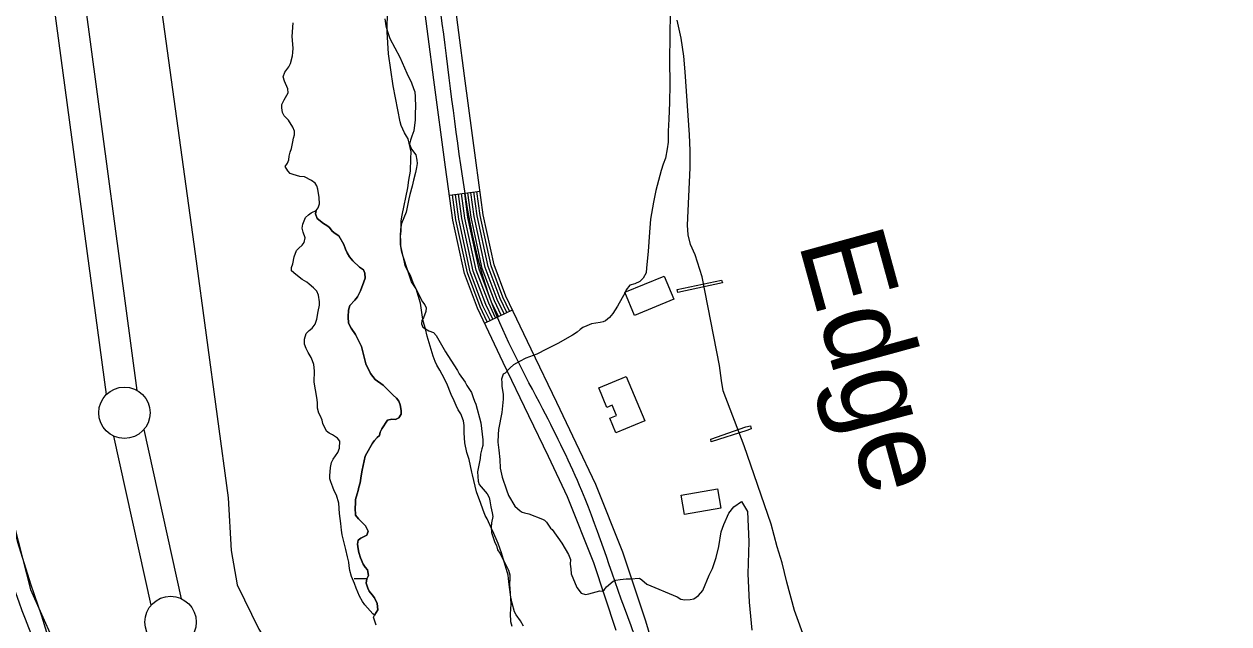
# Model space of a CAD drawing. Extents: x 3161564 to 3199464, y 849354 to 874788.
# Drawn here: x 3174720 to 3175892, y 859669 to 860252 of the extents above; entities that cross this region are included whole.
import ezdxf

# ---------------------------------------------------------------- set-up
doc = ezdxf.new("R2010")
doc.units = 0
for name, color, linetype in [('V-BLDG-OTLN', 7, 'Continuous'), ('V-CHAN-DOCK', 7, 'Continuous'), ('V-LEVE-TOET', 7, 'Continuous'), ('V-RIVR-IDEN', 7, 'Continuous'), ('V-ROAD-CNTR', 7, 'Continuous'), ('V-SITE-VEGE', 7, 'Continuous'), ('V-SURV-LINE', 7, 'Continuous'), ('V-TOPO-SHOR', 7, 'Continuous'), ('V-WETL-SWMP', 7, 'Continuous')]:
    doc.layers.add(name, color=color, linetype=linetype)

msp = doc.modelspace()

# ---------------------------------------------------------------- linework, layer by layer
at = {"layer": 'V-BLDG-OTLN'}
for points in [[(3175313.7, 859969.1), (3175304.4, 859991.7), (3175342.5, 860007.4), (3175351.8, 859984.8)], [(3175305.7, 859909.7), (3175323.7, 859866.5), (3175295.5, 859854.8), (3175289.6, 859869), (3175296.1, 859871.7), (3175291.9, 859881.8), (3175286.7, 859879.6), (3175278.9, 859898.5)], [(3175397.6, 859781.7), (3175362.3, 859775.4), (3175358.9, 859794.1), (3175394.2, 859800.5)]]:
    msp.add_lwpolyline(points, close=True, dxfattribs=at)
at = {"layer": 'V-CHAN-DOCK'}
for points in [[(3175398.3, 860003.2), (3175399.1, 860000.7), (3175355.7, 859991.5), (3175355.2, 859994.3), (3175398.3, 860003.2)], [(3175427.2, 859858.7), (3175422.8, 859857.2), (3175388.3, 859846.1), (3175387.8, 859848.8), (3175422, 859860.6), (3175426.3, 859861.6), (3175427.2, 859858.7)]]:
    msp.add_lwpolyline(points, dxfattribs=at)
at = {"layer": 'V-LEVE-TOET'}
for points in [[(3174822.8, 860492.3), (3174886.6, 860028.8), (3174918.6, 859791.7), (3174921.6, 859740.6), (3174927.3, 859707.2), (3174948.6, 859664), (3174965.5, 859636.6), (3174988.5, 859602.2), (3175016.5, 859565.4), (3175046.5, 859530.1), (3175135.4, 859413.8), (3175254.4, 859247.9), (3175400.5, 859075)], [(3175459.5, 858433.4), (3175350.4, 858733.6), (3175314.5, 858825.1), (3175277.8, 858898.4), (3175238, 858970.2), (3175193.8, 859031.2), (3175113.9, 859131.1), (3174929.1, 859367), (3174810.7, 859521.6), (3174784.7, 859565), (3174763.7, 859601.7), (3174748.5, 859640.6), (3174737.5, 859676.7), (3174726.8, 859707.8), (3174714.3, 859748.2), (3174706.3, 859779.3), (3174701.8, 859809.9), (3174688.7, 859906), (3174645.1, 860283.3)]]:
    msp.add_lwpolyline(points, dxfattribs=at)
at = {"layer": 'V-ROAD-CNTR'}
for p, q in [((3175133.7, 860085.9), (3175163.5, 860089.9)), ((3175167.9, 859961.5), (3175195, 859974.4))]:
    msp.add_line(p, q, dxfattribs=at)
for points in [[(3175335.6, 859596.5), (3175337, 859622.9), (3175335.1, 859636.8), (3175324.6, 859671.7), (3175302.2, 859738.8), (3175276.2, 859804.6), (3175257.1, 859844.7), (3175238.2, 859884.3), (3175213.2, 859936.4), (3175188.5, 859987.9), (3175177.1, 860018.2), (3175166.6, 860066.8), (3175159.7, 860117.4), (3175148.4, 860202), (3175137.5, 860286.7), (3175119.8, 860428.4), (3175103.4, 860569.6), (3175101.8, 860636.7), (3175101.3, 860705.2), (3175094.9, 860781), (3175087.1, 860856.3), (3175076.9, 860929.1)], [(3175296, 859662.7), (3175274, 859728.5), (3175248.6, 859792.6), (3175230, 859831.8), (3175211.1, 859871.4), (3175186.1, 859923.4), (3175160.9, 859976.1), (3175148.3, 860009.7), (3175137.1, 860061.6), (3175130, 860113.4), (3175118.7, 860198.1), (3175107.7, 860282.9)], [(3175170.6, 859962.8), (3175163.7, 859977.3), (3175151.2, 860010.5), (3175140, 860062.1), (3175136.7, 860086.3)], [(3175173.3, 859964.1), (3175166.4, 859978.5), (3175154, 860011.4), (3175143, 860062.7), (3175139.7, 860086.7)], [(3175176, 859965.4), (3175169.2, 859979.7), (3175156.9, 860012.2), (3175145.9, 860063.2), (3175142.7, 860087.1)], [(3175178.7, 859966.7), (3175172, 859980.9), (3175159.8, 860013.1), (3175148.9, 860063.7), (3175145.6, 860087.5)], [(3175181.4, 859968), (3175174.7, 859982), (3175162.7, 860013.9), (3175151.8, 860064.2), (3175148.6, 860087.9)], [(3175184.1, 859969.3), (3175177.5, 859983.2), (3175165.6, 860014.8), (3175154.8, 860064.7), (3175151.6, 860088.3)], [(3175186.9, 859970.6), (3175180.2, 859984.4), (3175168.5, 860015.6), (3175157.8, 860065.3), (3175154.5, 860088.7)], [(3175189.6, 859971.9), (3175183, 859985.6), (3175171.4, 860016.5), (3175160.7, 860065.8), (3175157.5, 860089.1)], [(3175192.3, 859973.2), (3175185.8, 859986.7), (3175174.2, 860017.3), (3175163.7, 860066.3), (3175160.5, 860089.5)]]:
    msp.add_lwpolyline(points, dxfattribs=at)
msp.add_arc((3175389.6, 859928.1), 715, 188.1088, 210.7285, dxfattribs=at)
msp.add_spline([(3176879.1, 855651.9), (3176902.3, 855659.1), (3176934.1, 855667), (3176983.4, 855657.7), (3177040.7, 855639.1), (3177110.5, 855613.6), (3177170.6, 855601.8), (3177236.8, 855586.9), (3177274.8, 855573.5), (3177317.4, 855579.8), (3177362.6, 855595.7), (3177412, 855643.1), (3177451.7, 855679.2), (3177476.7, 855705.8), (3177478.3, 855737), (3177464.2, 855782.3), (3177430.8, 855833.4), (3177373, 855887.8), (3177287.8, 855954.8), (3177219.8, 855998.4), (3177153, 856039.4), (3177089.3, 856079.2), (3177023.4, 856134.3), (3176966.6, 856207.9), (3176895.2, 856290.1), (3176782.2, 856425.1), (3176693.2, 856545.3), (3176615.2, 856622.6), (3176543.9, 856726.5), (3176474.4, 856784.2), (3176414.4, 856823.6), (3176395.9, 856828), (3176350.8, 856806.2), (3176279.1, 856754.7), (3176211.6, 856707.4), (3176172.3, 856696.1), (3176141.1, 856702), (3176111.7, 856719.6), (3176032.6, 856777.4), (3175933.6, 856857.4), (3175839, 856930.3), (3175807.1, 856951.5), (3175770.1, 856958.7), (3175787.1, 856991.4), (3175795.1, 857040.7), (3175799.5, 857113.7), (3175810.8, 857206.9), (3175813.7, 857287.4), (3175807.8, 857386.8), (3175805.7, 857497.9), (3175801.9, 857543.6), (3175783.5, 857620.5), (3175760.2, 857716.1), (3175755.3, 857765.5), (3175754.5, 857815.6), (3175751.7, 857884.3), (3175756.3, 858015.5), (3175754.9, 858158.6), (3175753.1, 858270.8), (3175748.6, 858321.7), (3175736.5, 858372), (3175677.2, 858555.5), (3175602.2, 858747.1), (3175558.2, 858866.9), (3175502.5, 858986.2), (3175436.3, 859092.6), (3175371.2, 859185.1), (3175300.7, 859261.6), (3175219.1, 859367.2), (3175166.2, 859443.7), (3175175.3, 859507.1), (3175222, 859537.9), (3175285.3, 859568.3), (3175321.2, 859607.5), (3175310.3, 859667.2), (3175262.4, 859798.6), (3175224.6, 859877.9), (3175174.7, 859982), (3175144.8, 860115.4), (3175122.6, 860284.8), (3175088.4, 860568.6), (3175086.3, 860704.5), (3175072.2, 860854.5), (3175052.5, 860999.9), (3175047.5, 861166.8), (3175053.2, 861343.7), (3175066.7, 861550.4), (3175065.5, 861662.5), (3175040.2, 861767.8), (3175017.8, 861884.2), (3175008.4, 862033.9), (3174979.6, 862160.3), (3174952.1, 862274.6), (3174921.6, 862422.8), (3174897, 862525.5), (3174861.7, 862663.2), (3174841.1, 862738)], degree=3, dxfattribs=at)
at = {"layer": 'V-SITE-VEGE'}
for points in [[(3175160, 859797.6), (3175156.2, 859814), (3175155.5, 859816.6), (3175152.8, 859828.9), (3175150.6, 859835.6), (3175148.6, 859845.3), (3175148, 859855), (3175148.1, 859862), (3175147.4, 859866.5), (3175145, 859873.5), (3175142.4, 859877.3), (3175140.3, 859881.4), (3175138.5, 859885.9), (3175135.3, 859892.3), (3175131.4, 859902.7), (3175126.7, 859911.7), (3175124.5, 859915.8), (3175121.6, 859920.7), (3175119.8, 859924.4), (3175118.1, 859929.6), (3175112.1, 859949), (3175110.4, 859956.1), (3175108.3, 859963.5), (3175107.2, 859969.5), (3175105.6, 859981), (3175101.4, 859994.8), (3175097, 860001.6), (3175093.5, 860011.3), (3175088.9, 860026.5), (3175086.1, 860038.1), (3175086.3, 860045.9), (3175086.7, 860051.4), (3175086.9, 860061.1), (3175087.7, 860066.6), (3175093.4, 860093.2), (3175094.2, 860100.6), (3175095.8, 860109.5), (3175096.1, 860121.8), (3175096.5, 860128), (3175093.8, 860140.7), (3175092, 860143.3), (3175090.2, 860146.7), (3175086.9, 860153.8), (3175085.9, 860157.2), (3175079.1, 860192.5), (3175074.4, 860223.4), (3175073.2, 860244.9), (3175074, 860288.3)], [(3175348.4, 860264.1), (3175347.6, 860217.3), (3175348, 860193.6), (3175347.7, 860176.2), (3175347, 860159.9), (3175346.5, 860148.4), (3175346.3, 860137.6), (3175345.5, 860131), (3175343.8, 860122.1), (3175341.5, 860116.2), (3175339.5, 860109.9), (3175334.4, 860090.7), (3175332, 860079.3), (3175329.1, 860062.6), (3175328.2, 860050), (3175327.1, 860031.1), (3175325.4, 860015.2)], [(3175325.4, 860015.2), (3175324.9, 860010.4), (3175322.2, 860005.2), (3175318.8, 860002), (3175314, 859999.8), (3175309.1, 859998.4), (3175305.7, 859994), (3175304.6, 859991.4), (3175297.3, 859978.2), (3175292.7, 859970.9), (3175289.3, 859967.2), (3175285.6, 859963.9), (3175283.3, 859962.9), (3175280.3, 859962.2), (3175271.8, 859960.8), (3175267.3, 859959), (3175263.6, 859957.3), (3175260.9, 859955.4), (3175257.9, 859952.9), (3175253.4, 859950), (3175239.2, 859941.7), (3175235.1, 859939.9), (3175225.7, 859934.9), (3175221.2, 859932.7), (3175218.6, 859931.3), (3175208.2, 859927.4), (3175201.8, 859924.2), (3175196.2, 859920.9), (3175192.8, 859918), (3175187.9, 859912.9), (3175186, 859911.8), (3175184.5, 859907), (3175184.8, 859903.7), (3175184.7, 859900.3), (3175186.1, 859892.2), (3175186, 859887.7), (3175184.7, 859874.7), (3175181.4, 859858.1), (3175181, 859853.3), (3175180.9, 859845.9), (3175181.8, 859838.1), (3175182.8, 859828.8), (3175183, 859820.6), (3175185.1, 859811.7), (3175189.4, 859799.4), (3175191.1, 859793.8), (3175197.3, 859783.7), (3175202.4, 859779.1), (3175204.6, 859777.6), (3175206.8, 859777.2), (3175210.8, 859776), (3175224.1, 859771), (3175226.3, 859769.8), (3175228.1, 859767.9), (3175232.1, 859762.3), (3175233.6, 859760.8), (3175243, 859747.7), (3175249.5, 859736.4), (3175251.3, 859731.6), (3175251.2, 859727.1), (3175251.9, 859722.7), (3175252.2, 859717.8), (3175257.5, 859704.4), (3175261.9, 859698.8), (3175265.9, 859697.6), (3175269.3, 859698.3), (3175280.1, 859701.1), (3175282.7, 859701), (3175284.5, 859702.5), (3175286.4, 859705), (3175292.8, 859710.5), (3175295.5, 859711.6), (3175299.9, 859712.2), (3175305.5, 859712.9), (3175309.9, 859712.8), (3175318.5, 859713.4), (3175320.7, 859711.9), (3175325.8, 859707.7), (3175355.3, 859695.4), (3175358.8, 859693), (3175362.5, 859692.4), (3175367.7, 859692.7), (3175371.4, 859693.6), (3175376, 859696.6), (3175380.2, 859701.7), (3175386.3, 859716.4), (3175389.5, 859722.9), (3175393.2, 859733.7), (3175395.7, 859744.3), (3175398, 859758.7), (3175400.4, 859765.8), (3175405.3, 859776.6), (3175410.2, 859782.8), (3175417.6, 859788.2), (3175423.6, 859778.3), (3175424.8, 859749), (3175423.8, 859717.9), (3175425.2, 859690.3), (3175427.8, 859663.1)], [(3175205.7, 859666.7), (3175202.8, 859671.9), (3175198.8, 859677.9), (3175197, 859680.9), (3175194.6, 859689.1), (3175193.6, 859695.1), (3175191.9, 859707.3), (3175191.3, 859713.3), (3175190.9, 859716.6), (3175184.3, 859738.3), (3175181.1, 859747.2), (3175176.1, 859759.2), (3175174.6, 859761.8), (3175170.3, 859771.1), (3175168.5, 859774.5), (3175166.1, 859780.8), (3175164.3, 859786.1), (3175160, 859797.6)]]:
    msp.add_lwpolyline(points, dxfattribs=at)
at = {"layer": 'V-SURV-LINE'}
for points in [[(3174800.3, 859892.2), (3174750, 860267.4)], [(3174779.7, 860271.4), (3174830, 859896.2)], [(3174836.8, 859858.1), (3174873, 859693.6)], [(3174843.7, 859687.2), (3174807.5, 859851.6)]]:
    msp.add_lwpolyline(points, dxfattribs=at)
for centre in [(3174817.8, 859874.4), (3174862.7, 859670.9)]:
    msp.add_circle(centre, 25, dxfattribs=at)
at = {"layer": 'V-TOPO-SHOR'}
msp.add_line((3175060.1, 859675.7), (3175061, 859677.4), dxfattribs=at)
for points in [[(3175004.3, 860071.1), (3175006.3, 860073.7), (3175007.5, 860077.5), (3175007.1, 860083.7), (3175005.9, 860092), (3175004.9, 860095.1), (3175003.1, 860097.8), (3174999.8, 860100.3), (3174992.8, 860103.8), (3174988.5, 860104.3), (3174981.9, 860106), (3174979, 860107.1), (3174976.6, 860109.6), (3174974.2, 860113.9), (3174976.3, 860117.2), (3174977.7, 860120.5), (3174977.9, 860124.1), (3174978.9, 860127.9), (3174980.3, 860131.4), (3174981.7, 860137.8), (3174982.2, 860141.4), (3174983.2, 860144.7), (3174983.2, 860148.3), (3174981.5, 860152.1), (3174977.2, 860158.9), (3174973.2, 860163.2), (3174971.5, 860166.3), (3174970.7, 860170.8), (3174970.8, 860174.3), (3174973.1, 860178.8), (3174977, 860185.6), (3174976.8, 860189.4), (3174973.4, 860196.8), (3174972.3, 860201.1), (3174973.7, 860205.7), (3174977.8, 860210.8), (3174979.4, 860214.1), (3174981.1, 860221.4), (3174981.6, 860224.7), (3174981.9, 860229), (3174981, 860240.4), (3174981.9, 860253.5)], [(3175071.1, 860257.6), (3175072.1, 860250.7), (3175073.5, 860245.1), (3175075.9, 860238.3), (3175085.6, 860220.1), (3175092.3, 860204.6), (3175097, 860195.4), (3175098.9, 860189.6), (3175100.2, 860186.5), (3175100.6, 860181.5), (3175100.8, 860171.7), (3175100.3, 860166), (3175100.6, 860159.3), (3175099.3, 860148.6), (3175097.3, 860143.5), (3175095.9, 860139.5), (3175095.1, 860135.5), (3175096.8, 860130.6), (3175101, 860125.2), (3175102.2, 860120.2), (3175102.4, 860116.7), (3175101.9, 860112.9), (3175100.9, 860108), (3175098.8, 860100.5), (3175097.6, 860094.7), (3175095.4, 860086.7), (3175094.2, 860082.3), (3175091.6, 860069.6), (3175089.5, 860064.1), (3175087.2, 860058.5), (3175086.2, 860053), (3175085.8, 860046.5), (3175086.2, 860041.8), (3175086.3, 860036.5), (3175086.7, 860032.3), (3175088.4, 860026.7), (3175089.9, 860020.8), (3175090.5, 860017.5), (3175092.9, 860012.8), (3175095.7, 860008.3), (3175098.2, 860001.1), (3175100.8, 859995.7), (3175107.7, 859982.2), (3175109.7, 859979.5), (3175111.2, 859976.4), (3175110.7, 859973), (3175108.4, 859966.8), (3175106.8, 859964.2), (3175106.5, 859960.9), (3175107.8, 859957.5), (3175110.4, 859955.9), (3175113.9, 859954), (3175118.4, 859952.4), (3175121, 859949.5), (3175129.9, 859933.5), (3175138.1, 859921.1), (3175141.6, 859915.5), (3175143.3, 859912.3), (3175149.2, 859904), (3175150.7, 859900.8), (3175155.1, 859894.1), (3175157, 859889.4), (3175158.3, 859885.8), (3175159.5, 859882.9), (3175164.4, 859864.7), (3175166.1, 859848), (3175166.2, 859842.7), (3175165.3, 859839.3), (3175164.1, 859834), (3175163.6, 859830), (3175160.9, 859816.9)], [(3175479.8, 859652.5), (3175469.3, 859682.1), (3175461.8, 859709.6), (3175457.3, 859728.3), (3175452.5, 859744.1), (3175446.6, 859766.1), (3175420.2, 859842.2), (3175399.9, 859895.6), (3175398.2, 859905.8), (3175396.2, 859920.4), (3175379.5, 860006.6), (3175372.5, 860028.1), (3175368.2, 860038), (3175365.8, 860047.5), (3175365.1, 860056.8), (3175367.9, 860112.7), (3175367.7, 860129.6), (3175367, 860144.7), (3175362.9, 860206.1), (3175361.7, 860221.3), (3175359.1, 860238.7), (3175355.3, 860256.1)], [(3175061, 859677.4), (3175064.2, 859682.6), (3175063.6, 859688.8), (3175060.8, 859694.4), (3175058.6, 859697.4), (3175055.8, 859700.8), (3175054.3, 859703.9), (3175052.8, 859708.6), (3175053.6, 859712.8), (3175055.2, 859716.1), (3175054.1, 859721.7), (3175052, 859724.2), (3175050, 859727.2), (3175047.2, 859733.4), (3175045.7, 859738.6), (3175044.9, 859742.2), (3175044.3, 859746.6), (3175045, 859750.4), (3175047.7, 859752.4), (3175053.4, 859755.2), (3175054.8, 859759.4), (3175052.2, 859764.3), (3175045.4, 859771.1), (3175042.6, 859774.7), (3175042.2, 859782.1), (3175042.3, 859786.3), (3175042.6, 859789.9), (3175044, 859795.4), (3175045.2, 859798.8), (3175045.7, 859801.9), (3175047.1, 859806.1), (3175047.9, 859813.2), (3175048.8, 859818.5), (3175052, 859832.1), (3175053.6, 859835.2), (3175059.1, 859844.7), (3175060.9, 859847.5), (3175063.4, 859850.4), (3175065.9, 859852.3), (3175066.4, 859855.5), (3175068, 859858.8), (3175073.5, 859867.1), (3175077.8, 859868.2), (3175081.5, 859867.9), (3175084.7, 859869.4), (3175086.7, 859872.9), (3175086.8, 859876.7), (3175085.8, 859882.1), (3175084.7, 859885.7), (3175082.3, 859888.6), (3175079, 859891.6), (3175071.6, 859899), (3175069.2, 859901.1), (3175061.5, 859906.6), (3175057.1, 859912.6), (3175052.6, 859922.1), (3175048.2, 859938.9), (3175042.4, 859950.6), (3175038.4, 859956.6), (3175035.8, 859961.4), (3175035.3, 859967.8), (3175035.6, 859974.3), (3175036.8, 859978.7), (3175041.8, 859983.8), (3175044.5, 859987.1), (3175047.3, 859993), (3175050.6, 860001.7), (3175051.7, 860005.4), (3175051.6, 860010.1), (3175050.1, 860013.5), (3175046.3, 860016), (3175040, 860022.1), (3175036.7, 860026.2), (3175034.3, 860029.8), (3175032.6, 860033.6), (3175031.1, 860038.1), (3175026.1, 860046.6), (3175022.8, 860048.7), (3175019.7, 860051), (3175017.1, 860054.6), (3175014.7, 860056.4), (3175011.2, 860058.5), (3175005.2, 860063.3), (3175003.5, 860067.7), (3175004.3, 860071.1)], [(3175160.9, 859816.9), (3175161.6, 859808), (3175162.7, 859804.6), (3175170.6, 859795.6), (3175172.5, 859792), (3175173.1, 859788.8), (3175173.9, 859782.8), (3175175.4, 859777.2), (3175175.8, 859773.6), (3175174.6, 859767.4), (3175174.3, 859763.2), (3175174.6, 859757.8), (3175178, 859748.2), (3175179.5, 859745.3), (3175180.6, 859741), (3175182.8, 859737.9), (3175189, 859725.7), (3175191.2, 859721.2), (3175192.4, 859716.8), (3175192.6, 859713.4), (3175192.1, 859707.2), (3175192.4, 859703.8), (3175193.5, 859688.4), (3175193, 859683.3), (3175192.9, 859678.9), (3175193.2, 859671.5), (3175194.5, 859666.8)], [(3174710.5, 859764.8), (3174726.5, 859702.6), (3174747.8, 859654.7), (3174763.8, 859619.2), (3174779.8, 859581.9), (3174806.4, 859535.7), (3174927.2, 859370.5), (3175088.9, 859169.7), (3175149.3, 859086.2), (3175236.3, 858969), (3175278.9, 858899.7), (3175328.7, 858796.7), (3175358.9, 858731)], [(3175062.6, 859667.7), (3175060.1, 859675.7)]]:
    msp.add_lwpolyline(points, dxfattribs=at)
at = {"layer": 'V-WETL-SWMP'}
msp.add_line((3175041.1, 859713.3), (3175053.8, 859713.3), dxfattribs=at)
for points in [[(3175061, 859677.4), (3175059.3, 859678.9), (3175051.4, 859687.5), (3175049.4, 859690.7), (3175046.4, 859696.1), (3175043, 859703.7), (3175041.5, 859708.4), (3175038.7, 859715.2), (3175036.8, 859721), (3175036.2, 859725.4), (3175036, 859729), (3175034.8, 859734.4), (3175032.9, 859741.3), (3175029.6, 859755.6), (3175028.8, 859760.3), (3175028.4, 859763.5), (3175028.2, 859766.8), (3175026.8, 859776.4), (3175026.3, 859786.4), (3175024, 859794.3), (3175021.8, 859798.5), (3175020.3, 859802.1), (3175018.4, 859807.1), (3175017.6, 859810), (3175017.4, 859813.1), (3175018, 859821.3), (3175019.2, 859826), (3175020.6, 859829.3), (3175025.3, 859835.9), (3175026.8, 859840.1), (3175027.3, 859846.8), (3175024.9, 859849.7), (3175020.1, 859852.9), (3175016.7, 859854.6), (3175014.3, 859856.6), (3175010.7, 859863.8), (3175010, 859867.2), (3175008.5, 859871), (3175006.8, 859874.1), (3175005.6, 859878.8), (3175005.4, 859884.4), (3175004.8, 859889.1), (3175002.2, 859904), (3175002.6, 859915.2), (3175002, 859921.2), (3175000.8, 859925), (3174999.2, 859928.2), (3174996.4, 859933.1), (3174994.5, 859936.9), (3174992.8, 859941), (3174992.9, 859946.1), (3174994.5, 859951.4), (3174997.5, 859954.5), (3175000.2, 859956.7), (3175003.1, 859960.4), (3175005, 859965.3), (3175006.2, 859972.8), (3175007.4, 859979.1), (3175007.3, 859982.2), (3175006.5, 859988.6), (3175005, 859992.5), (3175001.7, 859995.9), (3174997.5, 859999.5), (3174995.1, 860001.3), (3174990.7, 860004.1), (3174984.3, 860008.9), (3174980.1, 860012.5), (3174980.4, 860015.8), (3174981.4, 860019.1), (3174982.8, 860026), (3174985.2, 860032.2), (3174987.4, 860034.6), (3174990.6, 860037.5), (3174992.4, 860040.1), (3174993.6, 860044.6), (3174991.7, 860050), (3174990.6, 860053.8), (3174991.4, 860057.8), (3174992.5, 860060.9), (3174993.9, 860064.2), (3174996.7, 860067), (3174999.4, 860068.8), (3175004.3, 860071.1), (3175003.5, 860067.7), (3175005.2, 860063.3), (3175011.2, 860058.5), (3175014.7, 860056.4), (3175017.1, 860054.6), (3175019.7, 860051), (3175022.8, 860048.7), (3175026.1, 860046.6), (3175031.1, 860038.1), (3175032.6, 860033.6), (3175034.3, 860029.8), (3175036.7, 860026.2), (3175040, 860022.1), (3175046.3, 860016), (3175050.1, 860013.5), (3175051.6, 860010.1), (3175051.7, 860005.4), (3175050.6, 860001.7)], [(3175050.6, 860001.7), (3175047.3, 859993), (3175044.5, 859987.1), (3175041.8, 859983.8), (3175036.8, 859978.7), (3175035.6, 859974.3), (3175035.3, 859967.8), (3175035.8, 859961.4), (3175038.4, 859956.6), (3175042.4, 859950.6), (3175048.2, 859938.9), (3175052.6, 859922.1), (3175057.1, 859912.6), (3175061.5, 859906.6), (3175069.2, 859901.1), (3175071.6, 859899), (3175079, 859891.6), (3175082.3, 859888.6), (3175084.7, 859885.7), (3175085.8, 859882.1), (3175086.8, 859876.7), (3175086.7, 859872.9), (3175084.7, 859869.4), (3175081.5, 859867.9), (3175077.8, 859868.2), (3175073.5, 859867.1), (3175068, 859858.8), (3175066.4, 859855.5), (3175065.9, 859852.3), (3175063.4, 859850.4), (3175060.9, 859847.5), (3175059.1, 859844.7), (3175053.6, 859835.2), (3175052, 859832.1), (3175048.8, 859818.5), (3175047.9, 859813.2), (3175047.1, 859806.1), (3175045.7, 859801.9), (3175045.2, 859798.8), (3175044, 859795.4), (3175042.6, 859789.9), (3175042.3, 859786.3), (3175042.2, 859782.1), (3175042.6, 859774.7), (3175045.4, 859771.1), (3175052.2, 859764.3), (3175054.8, 859759.4), (3175053.4, 859755.2), (3175047.7, 859752.4), (3175045, 859750.4), (3175044.3, 859746.6), (3175044.9, 859742.2), (3175045.7, 859738.6), (3175047.2, 859733.4), (3175050, 859727.2), (3175052, 859724.2), (3175054.1, 859721.7), (3175055.2, 859716.1), (3175053.6, 859712.8), (3175052.8, 859708.6), (3175054.3, 859703.9), (3175055.8, 859700.8), (3175058.6, 859697.4), (3175060.8, 859694.4), (3175063.6, 859688.8), (3175064.2, 859682.6), (3175061, 859677.4)]]:
    msp.add_lwpolyline(points, dxfattribs=at)

# ---------------------------------------------------------------- texts
at = {"layer": 'V-RIVR-IDEN'}
msp.add_text('Edge', height=83, rotation=285.3382, dxfattribs=at).set_placement((3175472.8, 860039.8))

doc.saveas('drawing.dxf')
